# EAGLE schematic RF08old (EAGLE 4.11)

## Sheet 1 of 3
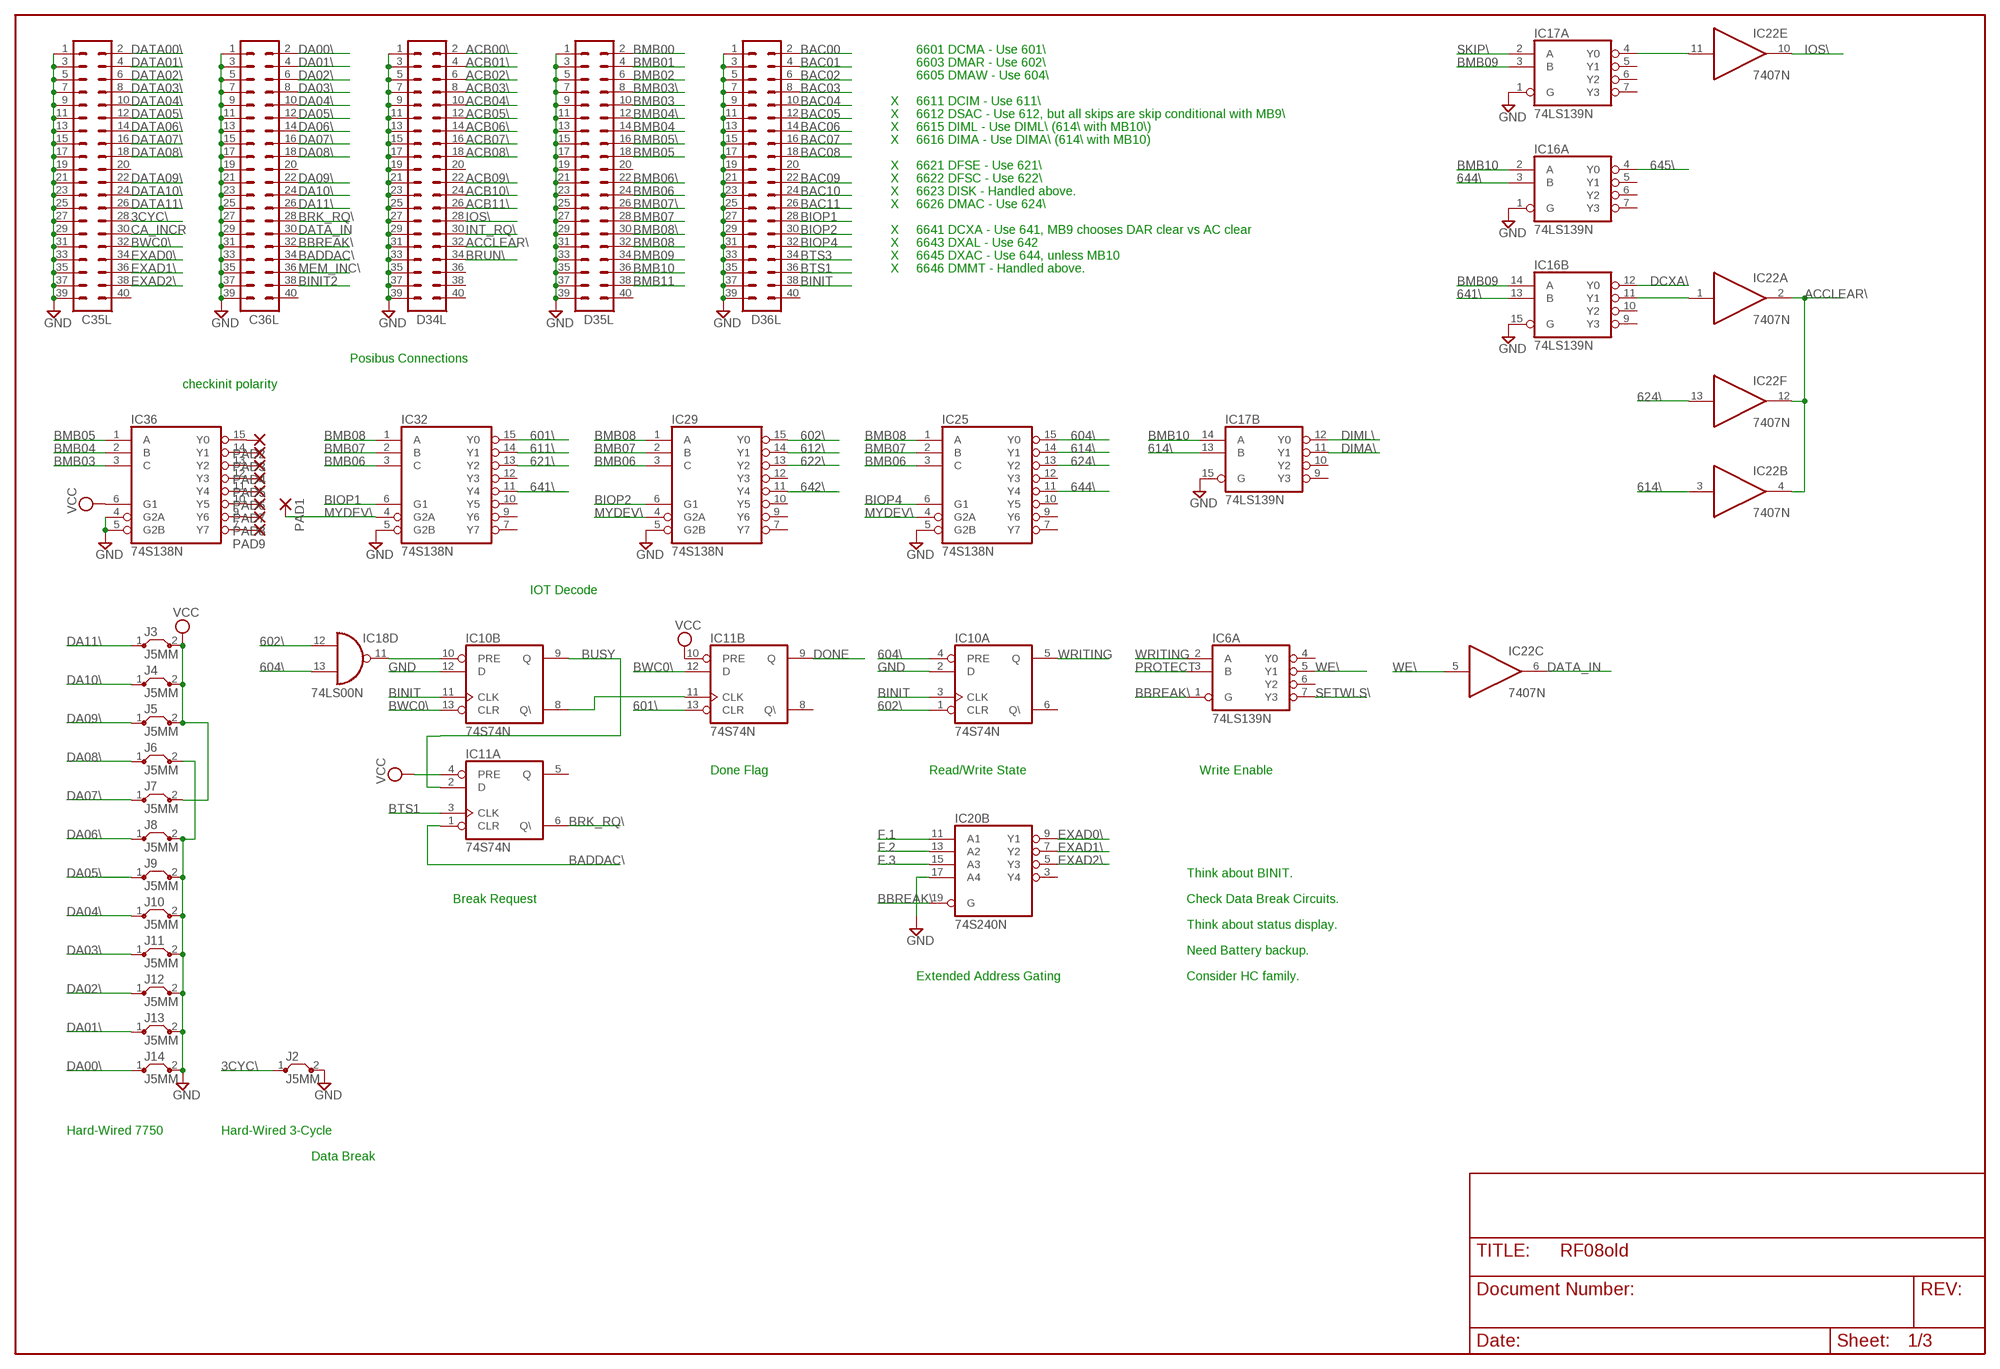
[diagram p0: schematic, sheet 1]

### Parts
C35L  MA20-2  [MA20-2]
C36L  MA20-2  [MA20-2]
D34L  MA20-2  [MA20-2]
D35L  MA20-2  [MA20-2]
D36L  MA20-2  [MA20-2]
IC6  74LS139N  74S139N  [DIL16]
IC10  74S74N  [DIL14]
IC11  74S74N  [DIL14]
IC16  74LS139N  74S139N  [DIL16]
IC17  74LS139N  74S139N  [DIL16]
IC18  74LS00N  [DIL14]
IC20  74S240N  [DIL20]
IC22  7407N  [DIL14]
IC25  74S138N  [DIL16]
IC29  74S138N  [DIL16]
IC32  74S138N  [DIL16]
IC36  74S138N  [DIL16]
J2  J5MM  [05]
J3  J5MM  [05]
J4  J5MM  [05]
J5  J5MM  [05]
J6  J5MM  [05]
J7  J5MM  [05]
J8  J5MM  [05]
J9  J5MM  [05]
J10  J5MM  [05]
J11  J5MM  [05]
J12  J5MM  [05]
J13  J5MM  [05]
J14  J5MM  [05]
PAD1  1,6/0,8  [1,6/0,8]
PAD2  1,6/0,8  [1,6/0,8]
PAD3  1,6/0,8  [1,6/0,8]
PAD4  1,6/0,8  [1,6/0,8]
PAD5  1,6/0,8  [1,6/0,8]
PAD6  1,6/0,8  [1,6/0,8]
PAD7  1,6/0,8  [1,6/0,8]
PAD8  1,6/0,8  [1,6/0,8]
PAD9  1,6/0,8  [1,6/0,8]

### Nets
3CYC\: C35L.28 J2.1
601\: IC11.13(B:CLR) IC32.15(Y0) ; also sheet 2
602\: IC10.1(A:CLR) IC18.12(D:I0) IC29.15(Y0) ; also sheet 2
604\: IC10.4(A:PRE) IC18.13(D:I1) IC25.15(Y0) ; also sheet 2
611\: IC32.14(Y1) ; also sheet 2
612\: IC29.14(Y1) ; also sheet 2
614\: IC17.13(B:B) IC22.3(B:I) IC25.14(Y1)
621\: IC32.13(Y2) ; also sheet 2
622\: IC29.13(Y2) ; also sheet 2
624\: IC22.13(F:I) IC25.13(Y2) ; also sheet 2
641\: IC16.13(B:B) IC32.11(Y4)
642\: IC29.11(Y4) ; also sheet 2
644\: IC16.3(A:B) IC25.11(Y4)
645\: IC16.4(A:Y0) ; also sheet 2
ACB00\: D34L.2 ; also sheet 2
ACB01\: D34L.4 ; also sheet 2
ACB02\: D34L.6 ; also sheet 2
ACB03\: D34L.8 ; also sheet 2
ACB04\: D34L.10 ; also sheet 2
ACB05\: D34L.12 ; also sheet 2
ACB06\: D34L.14 ; also sheet 2
ACB07\: D34L.16 ; also sheet 2
ACB08\: D34L.18 ; also sheet 2
ACB09\: D34L.22 ; also sheet 2
ACB10\: D34L.24 ; also sheet 2
ACB11\: D34L.26 ; also sheet 2
ACCLEAR\: D34L.32 IC22.2(A:O) IC22.4(B:O) IC22.12(F:O)
BAC00: D36L.2 ; also sheet 2
BAC01: D36L.4 ; also sheet 2
BAC02: D36L.6 ; also sheet 2
BAC03: D36L.8 ; also sheet 2
BAC04: D36L.10 ; also sheet 2
BAC05: D36L.12 ; also sheet 2
BAC06: D36L.14 ; also sheet 2
BAC07: D36L.16 ; also sheet 2
BAC08: D36L.18 ; also sheet 2
BAC09: D36L.22 ; also sheet 2
BAC10: D36L.24 ; also sheet 2
BAC11: D36L.26 ; also sheet 2
BADDAC\: C36L.34 IC11.1(A:CLR)
BBREAK\: C36L.32 IC6.1(A:G) IC20.19(B:G) ; also sheet 2,3
BINIT: D36L.38 IC10.3(A:CLK) IC10.11(B:CLK) ; also sheet 2
BINIT2: C36L.38
BIOP1: D36L.28 IC32.6(G1)
BIOP2: D36L.30 IC29.6(G1)
BIOP4: D36L.32 IC25.6(G1)
BMB00: D35L.2 ; also sheet 3
BMB01: D35L.4 ; also sheet 3
BMB02: D35L.6 ; also sheet 3
BMB03: D35L.10 IC36.3(C) ; also sheet 3
BMB03\: D35L.8
BMB04: D35L.14 IC36.2(B) ; also sheet 3
BMB04\: D35L.12
BMB05: D35L.18 IC36.1(A) ; also sheet 3
BMB05\: D35L.16
BMB06: D35L.24 IC25.3(C) IC29.3(C) IC32.3(C) ; also sheet 3
BMB06\: D35L.22
BMB07: D35L.28 IC25.2(B) IC29.2(B) IC32.2(B) ; also sheet 3
BMB07\: D35L.26
BMB08: D35L.32 IC25.1(A) IC29.1(A) IC32.1(A) ; also sheet 3
BMB08\: D35L.30
BMB09: D35L.34 IC16.14(B:A) IC17.3(A:B) ; also sheet 3
BMB10: D35L.36 IC16.2(A:A) IC17.14(B:A) ; also sheet 3
BMB11: D35L.38 ; also sheet 3
BRK_RQ\: C36L.28 IC11.6(A:Q\) ; also sheet 3
BRUN\: D34L.34
BTS1: D36L.36 IC11.3(A:CLK)
BTS3: D36L.34
BUSY: IC10.9(B:Q) IC11.2(A:D) ; also sheet 2
BWC0\: C35L.32 IC10.13(B:CLR) IC11.12(B:D) ; also sheet 3
CA_INCR: C35L.30
DA00\: C36L.2 J14.1
DA01\: C36L.4 J13.1
DA02\: C36L.6 J12.1
DA03\: C36L.8 J11.1
DA04\: C36L.10 J10.1
DA05\: C36L.12 J9.1
DA06\: C36L.14 J8.1
DA07\: C36L.16 J7.1
DA08\: C36L.18 J6.1
DA09\: C36L.22 J5.1
DA10\: C36L.24 J4.1
DA11\: C36L.26 J3.1
DATA00\: C35L.2 ; also sheet 3
DATA01\: C35L.4 ; also sheet 3
DATA02\: C35L.6 ; also sheet 3
DATA03\: C35L.8 ; also sheet 3
DATA04\: C35L.10 ; also sheet 3
DATA05\: C35L.12 ; also sheet 3
DATA06\: C35L.14 ; also sheet 3
DATA07\: C35L.16 ; also sheet 3
DATA08\: C35L.18 ; also sheet 3
DATA09\: C35L.22 ; also sheet 3
DATA10\: C35L.24 ; also sheet 3
DATA11\: C35L.26 ; also sheet 3
DATA_IN: C36L.30 IC22.6(C:O)
DCXA\: IC16.12(B:Y0) ; also sheet 2
DIMA\: IC17.11(B:Y1) ; also sheet 2
DIML\: IC17.12(B:Y0) ; also sheet 2
DONE: IC11.9(B:Q) ; also sheet 2,3
EXAD0\: C35L.34 IC20.9(B:Y1)
EXAD1\: C35L.36 IC20.7(B:Y2)
EXAD2\: C35L.38 IC20.5(B:Y3)
F.1: IC20.11(B:A1) ; also sheet 2,3
F.2: IC20.13(B:A2) ; also sheet 2,3
F.3: IC20.15(B:A3) ; also sheet 2,3
GND: C35L.1 C35L.3 C35L.5 C35L.7 C35L.9 C35L.11 C35L.13 C35L.15 C35L.17 C35L.19 C35L.21 C35L.23 C35L.25 C35L.27 C35L.29 C35L.31 C35L.33 C35L.35 C35L.37 C35L.39 C36L.1 C36L.3 C36L.5 C36L.7 C36L.9 C36L.11 C36L.13 C36L.15 C36L.17 C36L.19 C36L.21 C36L.23 C36L.25 C36L.27 C36L.29 C36L.31 C36L.33 C36L.35 C36L.37 C36L.39 D34L.1 D34L.3 D34L.5 D34L.7 D34L.9 D34L.11 D34L.13 D34L.15 D34L.17 D34L.19 D34L.21 D34L.23 D34L.25 D34L.27 D34L.29 D34L.31 D34L.33 D34L.35 D34L.37 D34L.39 D35L.1 D35L.3 D35L.5 D35L.7 D35L.9 D35L.11 D35L.13 D35L.15 D35L.17 D35L.19 D35L.21 D35L.23 D35L.25 D35L.27 D35L.29 D35L.31 D35L.33 D35L.35 D35L.37 D35L.39 D36L.1 D36L.3 D36L.5 D36L.7 D36L.9 D36L.11 D36L.13 D36L.15 D36L.17 D36L.19 D36L.21 D36L.23 D36L.25 D36L.27 D36L.29 D36L.31 D36L.33 D36L.35 D36L.37 D36L.39 IC10.2(A:D) IC10.12(B:D) IC16.1(A:G) IC16.15(B:G) IC17.1(A:G) IC17.15(B:G) IC20.17(B:A4) IC25.5(G2B) IC29.5(G2B) IC32.5(G2B) IC36.4(G2A) IC36.5(G2B) J2.2 J6.2 J8.2 J9.2 J10.2 J11.2 J12.2 J13.2 J14.2 ; also sheet 2,3
INT_RQ\: D34L.30 ; also sheet 2
IOS\: D34L.28 IC22.10(E:O)
MEM_INC\: C36L.36
MYDEV\: IC25.4(G2A) IC29.4(G2A) IC32.4(G2A) PAD1.1(P)
N$1: IC36.9(Y6) PAD8.1(P)
N$2: IC10.8(B:Q\) IC11.11(B:CLK)
N$5: IC36.15(Y0) PAD2.1(P)
N$6: IC36.14(Y1) PAD3.1(P)
N$7: IC36.13(Y2) PAD4.1(P)
N$8: IC36.12(Y3) PAD5.1(P)
N$9: IC36.11(Y4) PAD6.1(P)
N$10: IC36.10(Y5) PAD7.1(P)
N$11: IC36.7(Y7) PAD9.1(P)
N$26: IC16.11(B:Y1) IC22.1(A:I)
N$27: IC17.4(A:Y0) IC22.11(E:I)
N$31: IC10.10(B:PRE) IC18.11(D:O)
PROTECT: IC6.3(A:B) ; also sheet 3
SETWLS\: IC6.7(A:Y3) ; also sheet 2
SKIP\: IC17.2(A:A) ; also sheet 2
VCC [Power]: IC11.4(A:PRE) IC11.10(B:PRE) IC36.6(G1) J3.2 J4.2 J5.2 J7.2 ; also sheet 2,3
WE\: IC6.5(A:Y1) IC22.5(C:I) ; also sheet 3
WRITING: IC6.2(A:A) IC10.5(A:Q) ; also sheet 3
Unconnected: C35L.20 C35L.40 C36L.20 C36L.40 D34L.20 D34L.36 D34L.38 D34L.40 D35L.20 D35L.40 D36L.20 D36L.40 IC6.4(A:Y0) IC6.6(A:Y2) IC6.9(B:Y3) IC6.10(B:Y2) IC6.11(B:Y1) IC6.12(B:Y0) IC6.13(B:B) IC6.14(B:A) IC6.15(B:G) IC10.6(A:Q\) IC11.5(A:Q) IC11.8(B:Q\) IC16.5(A:Y1) IC16.6(A:Y2) IC16.7(A:Y3) IC16.9(B:Y3) IC16.10(B:Y2) IC17.5(A:Y1) IC17.6(A:Y2) IC17.7(A:Y3) IC17.9(B:Y3) IC17.10(B:Y2) IC20.1(A:G) IC20.2(A:A1) IC20.3(B:Y4) IC20.4(A:A2) IC20.6(A:A3) IC20.8(A:A4) IC20.12(A:Y4) IC20.14(A:Y3) IC20.16(A:Y2) IC20.18(A:Y1) IC22.8(D:O) IC22.9(D:I) IC25.7(Y7) IC25.9(Y6) IC25.10(Y5) IC25.12(Y3) IC29.7(Y7) IC29.9(Y6) IC29.10(Y5) IC29.12(Y3) IC32.7(Y7) IC32.9(Y6) IC32.10(Y5) IC32.12(Y3)

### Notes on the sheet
- 6601 DCMA - Use 601\
- 6603 DMAR - Use 602\
- 6605 DMAW - Use 604\
- X | 6611 DCIM - Use 611\
- X | 6612 DSAC - Use 612\, but all skips are skip conditional with MB9\
- X | 6615 DIML - Use DIML\ (614\ with MB10\)
- X | 6616 DIMA - Use DIMA\ (614\ with MB10)
- X | 6621 DFSE - Use 621\
- X | 6622 DFSC - Use 622\
- X | 6623 DISK - Handled above.
- X | 6626 DMAC - Use 624\
- X | 6641 DCXA - Use 641, MB9 chooses DAR clear vs AC clear
- X | 6643 DXAL - Use 642
- X | 6645 DXAC - Use 644, unless MB10
- X | 6646 DMMT - Handled above.
- Posibus Connections
- checkinit polarity
- IOT Decode
- Done Flag | Read/Write State | Write Enable
- Think about BINIT.
- Break Request | Check Data Break Circuits.
- Think about status display.
- Need Battery backup.
- Extended Address Gating | Consider HC family.
- Hard-Wired 7750 | Hard-Wired 3-Cycle
- Data Break

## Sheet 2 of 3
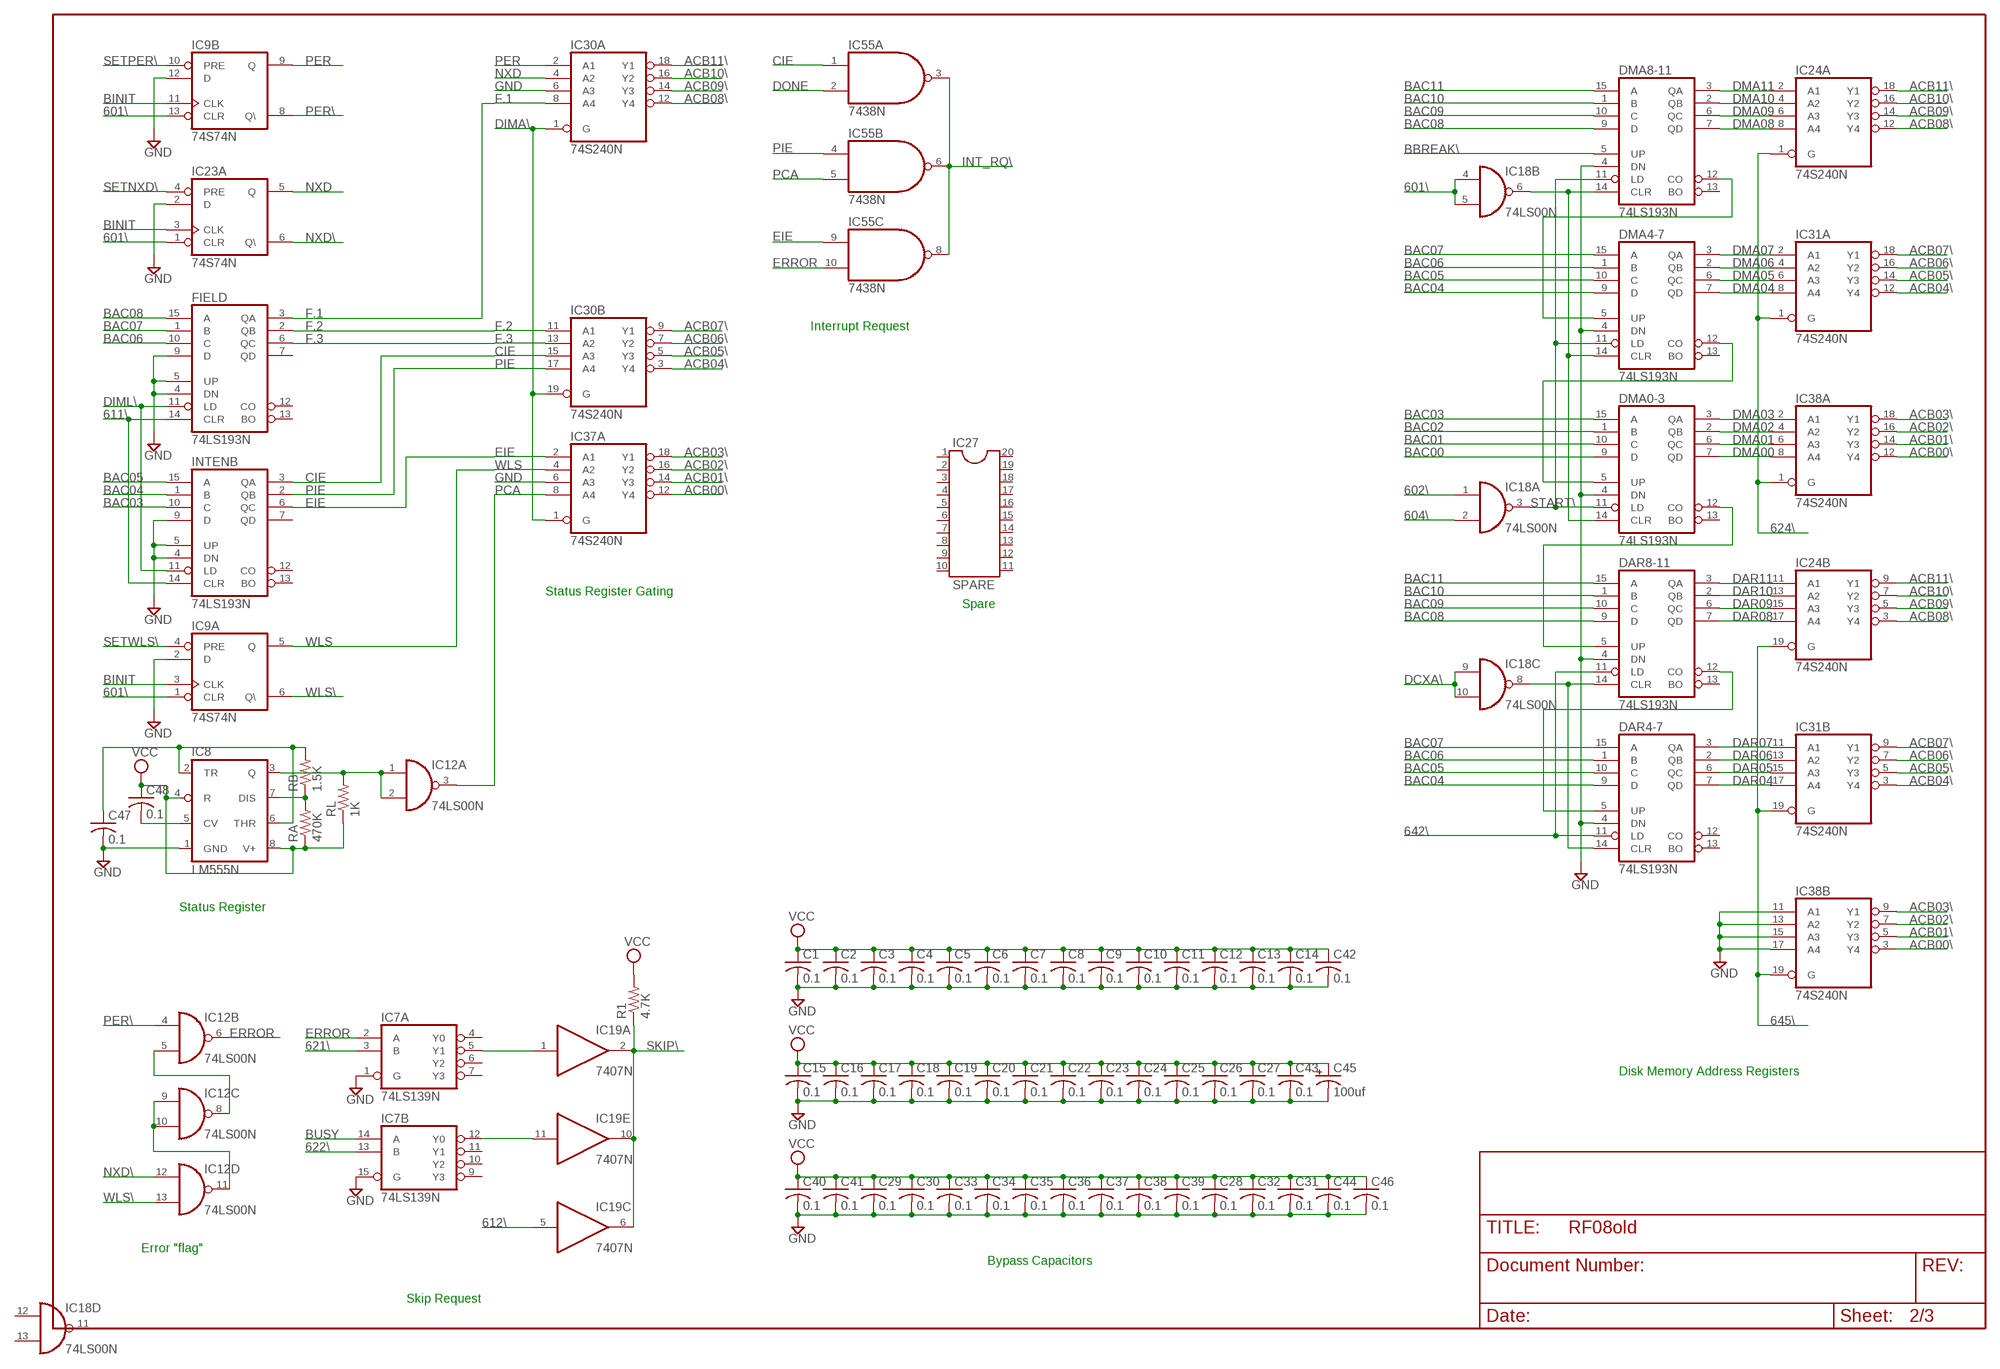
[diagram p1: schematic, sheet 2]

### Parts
C1  0.1  C-US050-025X075  [C050-025X075]
C2  0.1  C-US050-025X075  [C050-025X075]
C3  0.1  C-US050-025X075  [C050-025X075]
C4  0.1  C-US050-025X075  [C050-025X075]
C5  0.1  C-US050-025X075  [C050-025X075]
C6  0.1  C-US050-025X075  [C050-025X075]
C7  0.1  C-US050-025X075  [C050-025X075]
C8  0.1  C-US050-025X075  [C050-025X075]
C9  0.1  C-US050-025X075  [C050-025X075]
C10  0.1  C-US050-025X075  [C050-025X075]
C11  0.1  C-US050-025X075  [C050-025X075]
C12  0.1  C-US050-025X075  [C050-025X075]
C13  0.1  C-US050-025X075  [C050-025X075]
C14  0.1  C-US050-025X075  [C050-025X075]
C15  0.1  C-US050-025X075  [C050-025X075]
C16  0.1  C-US050-025X075  [C050-025X075]
C17  0.1  C-US050-025X075  [C050-025X075]
C18  0.1  C-US050-025X075  [C050-025X075]
C19  0.1  C-US050-025X075  [C050-025X075]
C20  0.1  C-US050-025X075  [C050-025X075]
C21  0.1  C-US050-025X075  [C050-025X075]
C22  0.1  C-US050-025X075  [C050-025X075]
C23  0.1  C-US050-025X075  [C050-025X075]
C24  0.1  C-US050-025X075  [C050-025X075]
C25  0.1  C-US050-025X075  [C050-025X075]
C26  0.1  C-US050-025X075  [C050-025X075]
C27  0.1  C-US050-025X075  [C050-025X075]
C28  0.1  C-US050-025X075  [C050-025X075]
C29  0.1  C-US050-025X075  [C050-025X075]
C30  0.1  C-US050-025X075  [C050-025X075]
C31  0.1  C-US050-025X075  [C050-025X075]
C32  0.1  C-US050-025X075  [C050-025X075]
C33  0.1  C-US050-025X075  [C050-025X075]
C34  0.1  C-US050-025X075  [C050-025X075]
C35  0.1  C-US050-025X075  [C050-025X075]
C36  0.1  C-US050-025X075  [C050-025X075]
C37  0.1  C-US050-025X075  [C050-025X075]
C38  0.1  C-US050-025X075  [C050-025X075]
C39  0.1  C-US050-025X075  [C050-025X075]
C40  0.1  C-US050-025X075  [C050-025X075]
C41  0.1  C-US050-025X075  [C050-025X075]
C42  0.1  C-US050-025X075  [C050-025X075]
C43  0.1  C-US050-025X075  [C050-025X075]
C44  0.1  C-US050-025X075  [C050-025X075]
C45  100uf  CPOL-USE22-6AXIAL  [E22-6]
C46  0.1  C-US050-025X075  [C050-025X075]
C47  0.1  C-US050-025X075  [C050-025X075]
C48  0.1  C-US050-025X075  [C050-025X075]
DAR4-7  74LS193N  74LS192N  [DIL16]
DAR8-11  74LS193N  74LS192N  [DIL16]
DMA0-3  74LS193N  74LS192N  [DIL16]
DMA4-7  74LS193N  74LS192N  [DIL16]
DMA8-11  74LS193N  74LS192N  [DIL16]
FIELD  74LS193N  74LS192N  [DIL16]
IC7  74LS139N  [DIL16]
IC8  LM555N  [DIL08]
IC9  74S74N  [DIL14]
IC12  74LS00N  [DIL14]
IC19  7407N  [DIL14]
IC23  74S74N  [DIL14]
IC24  74S240N  [DIL20]
IC27  SPARE  DIL20  [DIL20]
IC30  74S240N  [DIL20]
IC31  74S240N  [DIL20]
IC37  74S240N  [DIL20]
IC38  74S240N  [DIL20]
IC55  7438N  [DIL14]
INTENB  74LS193N  74LS192N  [DIL16]
R1  4.7K  R-US_0207/10  [0207/10]
RA  470K  R-US_0207/10  [0207/10]
RB  1.5K  R-US_0207/10  [0207/10]
RL  1K  R-US_0207/10  [0207/10]

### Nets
601\: IC9.1(A:CLR) IC9.13(B:CLR) IC18.4(B:I0) IC18.5(B:I1) IC23.1(A:CLR) ; also sheet 1
602\: IC18.1(A:I0) ; also sheet 1
604\: IC18.2(A:I1) ; also sheet 1
611\: FIELD.14(CLR) INTENB.14(CLR) ; also sheet 1
612\: IC19.5(C:I) ; also sheet 1
621\: IC7.3(A:B) ; also sheet 1
622\: IC7.13(B:B) ; also sheet 1
624\: IC24.1(A:G) IC31.1(A:G) IC38.1(A:G) ; also sheet 1
642\: DAR4-7.11(LD) DAR8-11.11(LD) ; also sheet 1
645\: IC24.19(B:G) IC31.19(B:G) IC38.19(B:G) ; also sheet 1
ACB00\: IC37.12(A:Y4) IC38.3(B:Y4) IC38.12(A:Y4) ; also sheet 1
ACB01\: IC37.14(A:Y3) IC38.5(B:Y3) IC38.14(A:Y3) ; also sheet 1
ACB02\: IC37.16(A:Y2) IC38.7(B:Y2) IC38.16(A:Y2) ; also sheet 1
ACB03\: IC37.18(A:Y1) IC38.9(B:Y1) IC38.18(A:Y1) ; also sheet 1
ACB04\: IC30.3(B:Y4) IC31.3(B:Y4) IC31.12(A:Y4) ; also sheet 1
ACB05\: IC30.5(B:Y3) IC31.5(B:Y3) IC31.14(A:Y3) ; also sheet 1
ACB06\: IC30.7(B:Y2) IC31.7(B:Y2) IC31.16(A:Y2) ; also sheet 1
ACB07\: IC30.9(B:Y1) IC31.9(B:Y1) IC31.18(A:Y1) ; also sheet 1
ACB08\: IC24.3(B:Y4) IC24.12(A:Y4) IC30.12(A:Y4) ; also sheet 1
ACB09\: IC24.5(B:Y3) IC24.14(A:Y3) IC30.14(A:Y3) ; also sheet 1
ACB10\: IC24.7(B:Y2) IC24.16(A:Y2) IC30.16(A:Y2) ; also sheet 1
ACB11\: IC24.9(B:Y1) IC24.18(A:Y1) IC30.18(A:Y1) ; also sheet 1
BAC00: DMA0-3.9(D) ; also sheet 1
BAC01: DMA0-3.10(C) ; also sheet 1
BAC02: DMA0-3.1(B) ; also sheet 1
BAC03: DMA0-3.15(A) INTENB.10(C) ; also sheet 1
BAC04: DAR4-7.9(D) DMA4-7.9(D) INTENB.1(B) ; also sheet 1
BAC05: DAR4-7.10(C) DMA4-7.10(C) INTENB.15(A) ; also sheet 1
BAC06: DAR4-7.1(B) DMA4-7.1(B) FIELD.10(C) ; also sheet 1
BAC07: DAR4-7.15(A) DMA4-7.15(A) FIELD.1(B) ; also sheet 1
BAC08: DAR8-11.9(D) DMA8-11.9(D) FIELD.15(A) ; also sheet 1
BAC09: DAR8-11.10(C) DMA8-11.10(C) ; also sheet 1
BAC10: DAR8-11.1(B) DMA8-11.1(B) ; also sheet 1
BAC11: DAR8-11.15(A) DMA8-11.15(A) ; also sheet 1
BBREAK\: DMA8-11.5(UP) ; also sheet 1,3
BINIT: IC9.3(A:CLK) IC9.11(B:CLK) IC23.3(A:CLK) ; also sheet 1
BUSY: IC7.14(B:A) ; also sheet 1
CIE: IC30.15(B:A3) IC55.1(A:I0) INTENB.3(QA) ; also sheet 3
DAR04: DAR4-7.7(QD) IC31.17(B:A4) ; also sheet 3
DAR05: DAR4-7.6(QC) IC31.15(B:A3) ; also sheet 3
DAR06: DAR4-7.2(QB) IC31.13(B:A2) ; also sheet 3
DAR07: DAR4-7.3(QA) IC31.11(B:A1) ; also sheet 3
DAR08: DAR8-11.7(QD) IC24.17(B:A4) ; also sheet 3
DAR09: DAR8-11.6(QC) IC24.15(B:A3) ; also sheet 3
DAR10: DAR8-11.2(QB) IC24.13(B:A2) ; also sheet 3
DAR11: DAR8-11.3(QA) IC24.11(B:A1) ; also sheet 3
DCXA\: IC18.9(C:I0) IC18.10(C:I1) ; also sheet 1
DIMA\: IC30.1(A:G) IC30.19(B:G) IC37.1(A:G) ; also sheet 1
DIML\: FIELD.11(LD) INTENB.11(LD) ; also sheet 1
DMA00: DMA0-3.7(QD) IC38.8(A:A4) ; also sheet 3
DMA01: DMA0-3.6(QC) IC38.6(A:A3) ; also sheet 3
DMA02: DMA0-3.2(QB) IC38.4(A:A2) ; also sheet 3
DMA03: DMA0-3.3(QA) IC38.2(A:A1) ; also sheet 3
DMA04: DMA4-7.7(QD) IC31.8(A:A4) ; also sheet 3
DMA05: DMA4-7.6(QC) IC31.6(A:A3) ; also sheet 3
DMA06: DMA4-7.2(QB) IC31.4(A:A2) ; also sheet 3
DMA07: DMA4-7.3(QA) IC31.2(A:A1) ; also sheet 3
DMA08: DMA8-11.7(QD) IC24.8(A:A4) ; also sheet 3
DMA09: DMA8-11.6(QC) IC24.6(A:A3) ; also sheet 3
DMA10: DMA8-11.2(QB) IC24.4(A:A2) ; also sheet 3
DMA11: DMA8-11.3(QA) IC24.2(A:A1) ; also sheet 3
DONE: IC55.2(A:I1) ; also sheet 1,3
EIE: IC37.2(A:A1) IC55.9(C:I0) INTENB.6(QC) ; also sheet 3
ERROR: IC7.2(A:A) IC12.6(B:O) IC55.10(C:I1)
F.1: FIELD.3(QA) IC30.8(A:A4) ; also sheet 1,3
F.2: FIELD.2(QB) IC30.11(B:A1) ; also sheet 1,3
F.3: FIELD.6(QC) IC30.13(B:A2) ; also sheet 1,3
GND: C1.2 C2.2 C3.2 C4.2 C5.2 C6.2 C7.2 C8.2 C9.2 C10.2 C11.2 C12.2 C13.2 C14.2 C15.2 C16.2 C17.2 C18.2 C19.2 C20.2 C21.2 C22.2 C23.2 C24.2 C25.2 C26.2 C27.2 C28.2 C29.2 C30.2 C31.2 C32.2 C33.2 C34.2 C35.2 C36.2 C37.2 C38.2 C39.2 C40.2 C41.2 C42.2 C43.2 C44.2 C45.- C46.2 C47.2 DAR4-7.4(DN) DAR8-11.4(DN) DMA0-3.4(DN) DMA4-7.4(DN) DMA8-11.4(DN) FIELD.4(DN) FIELD.5(UP) FIELD.9(D) IC7.1(A:G) IC7.15(B:G) IC8.1(GND) IC9.2(A:D) IC9.12(B:D) IC23.2(A:D) IC30.6(A:A3) IC37.6(A:A3) IC38.11(B:A1) IC38.13(B:A2) IC38.15(B:A3) IC38.17(B:A4) INTENB.4(DN) INTENB.5(UP) INTENB.9(D) ; also sheet 1,3
INT_RQ\: IC55.3(A:O) IC55.6(B:O) IC55.8(C:O) ; also sheet 1
N$3: DMA0-3.5(UP) DMA4-7.12(CO)
N$12: DAR4-7.14(CLR) DAR8-11.14(CLR) IC18.8(C:O)
N$13: DMA4-7.5(UP) DMA8-11.12(CO)
N$16: DAR8-11.5(UP) DMA0-3.12(CO)
N$22: DMA0-3.14(CLR) DMA4-7.14(CLR) DMA8-11.14(CLR) IC18.6(B:O)
N$25: DAR4-7.5(UP) DAR8-11.12(CO)
N$28: IC7.5(A:Y1) IC19.1(A:I)
N$29: IC8.7(DIS) RA.2 RB.1
N$30: IC8.3(Q) IC12.1(A:I0) IC12.2(A:I1) RL.2
N$32: C47.1 IC8.2(TR) IC8.6(THR) RB.2
N$33: IC7.12(B:Y0) IC19.11(E:I)
N$34: C48.2 IC8.5(CV)
N$37: IC12.9(C:I0) IC12.10(C:I1) IC12.11(D:O)
N$40: IC12.5(B:I1) IC12.8(C:O)
NXD: IC23.5(A:Q) IC30.4(A:A2) ; also sheet 3
NXD\: IC12.12(D:I0) IC23.6(A:Q\)
PCA: IC12.3(A:O) IC37.8(A:A4) IC55.5(B:I1)
PER: IC9.9(B:Q) IC30.2(A:A1) ; also sheet 3
PER\: IC9.8(B:Q\) IC12.4(B:I0)
PIE: IC30.17(B:A4) IC55.4(B:I0) INTENB.2(QB) ; also sheet 3
SETNXD\: IC23.4(A:PRE) ; also sheet 3
SETPER\: IC9.10(B:PRE) ; also sheet 3
SETWLS\: IC9.4(A:PRE) ; also sheet 1
SKIP\: IC19.2(A:O) IC19.6(C:O) IC19.10(E:O) R1.1 ; also sheet 1
START\: DMA0-3.11(LD) DMA4-7.11(LD) DMA8-11.11(LD) IC18.3(A:O)
VCC [Power]: C1.1 C2.1 C3.1 C4.1 C5.1 C6.1 C7.1 C8.1 C9.1 C10.1 C11.1 C12.1 C13.1 C14.1 C15.1 C16.1 C17.1 C18.1 C19.1 C20.1 C21.1 C22.1 C23.1 C24.1 C25.1 C26.1 C27.1 C28.1 C29.1 C30.1 C31.1 C32.1 C33.1 C34.1 C35.1 C36.1 C37.1 C38.1 C39.1 C40.1 C41.1 C42.1 C43.1 C44.1 C45.+ C46.1 C48.1 IC8.4(R) IC8.8(V+) R1.2 RA.1 RL.1 ; also sheet 1,3
WLS: IC9.5(A:Q) IC37.4(A:A2) ; also sheet 3
WLS\: IC9.6(A:Q\) IC12.13(D:I1)
Unconnected: DAR4-7.12(CO) DAR4-7.13(BO) DAR8-11.13(BO) DMA0-3.13(BO) DMA4-7.13(BO) DMA8-11.13(BO) FIELD.7(QD) FIELD.12(CO) FIELD.13(BO) IC7.4(A:Y0) IC7.6(A:Y2) IC7.7(A:Y3) IC7.9(B:Y3) IC7.10(B:Y2) IC7.11(B:Y1) IC19.3(B:I) IC19.4(B:O) IC19.8(D:O) IC19.9(D:I) IC19.12(F:O) IC19.13(F:I) IC23.8(B:Q\) IC23.9(B:Q) IC23.10(B:PRE) IC23.11(B:CLK) IC23.12(B:D) IC23.13(B:CLR) IC27.1 IC27.2 IC27.3 IC27.4 IC27.5 IC27.6 IC27.7 IC27.8 IC27.9 IC27.10 IC27.11 IC27.12 IC27.13 IC27.14 IC27.15 IC27.16 IC27.17 IC27.18 IC27.19 IC27.20 IC37.3(B:Y4) IC37.5(B:Y3) IC37.7(B:Y2) IC37.9(B:Y1) IC37.11(B:A1) IC37.13(B:A2) IC37.15(B:A3) IC37.17(B:A4) IC37.19(B:G) IC55.11(D:O) IC55.12(D:I0) IC55.13(D:I1) INTENB.7(QD) INTENB.12(CO) INTENB.13(BO)

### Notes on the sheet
- Interrupt Request
- Status Register Gating
- Spare
- Status Register
- Disk Memory Address Registers
- Error "flag"
- Bypass Capacitors
- Skip Request

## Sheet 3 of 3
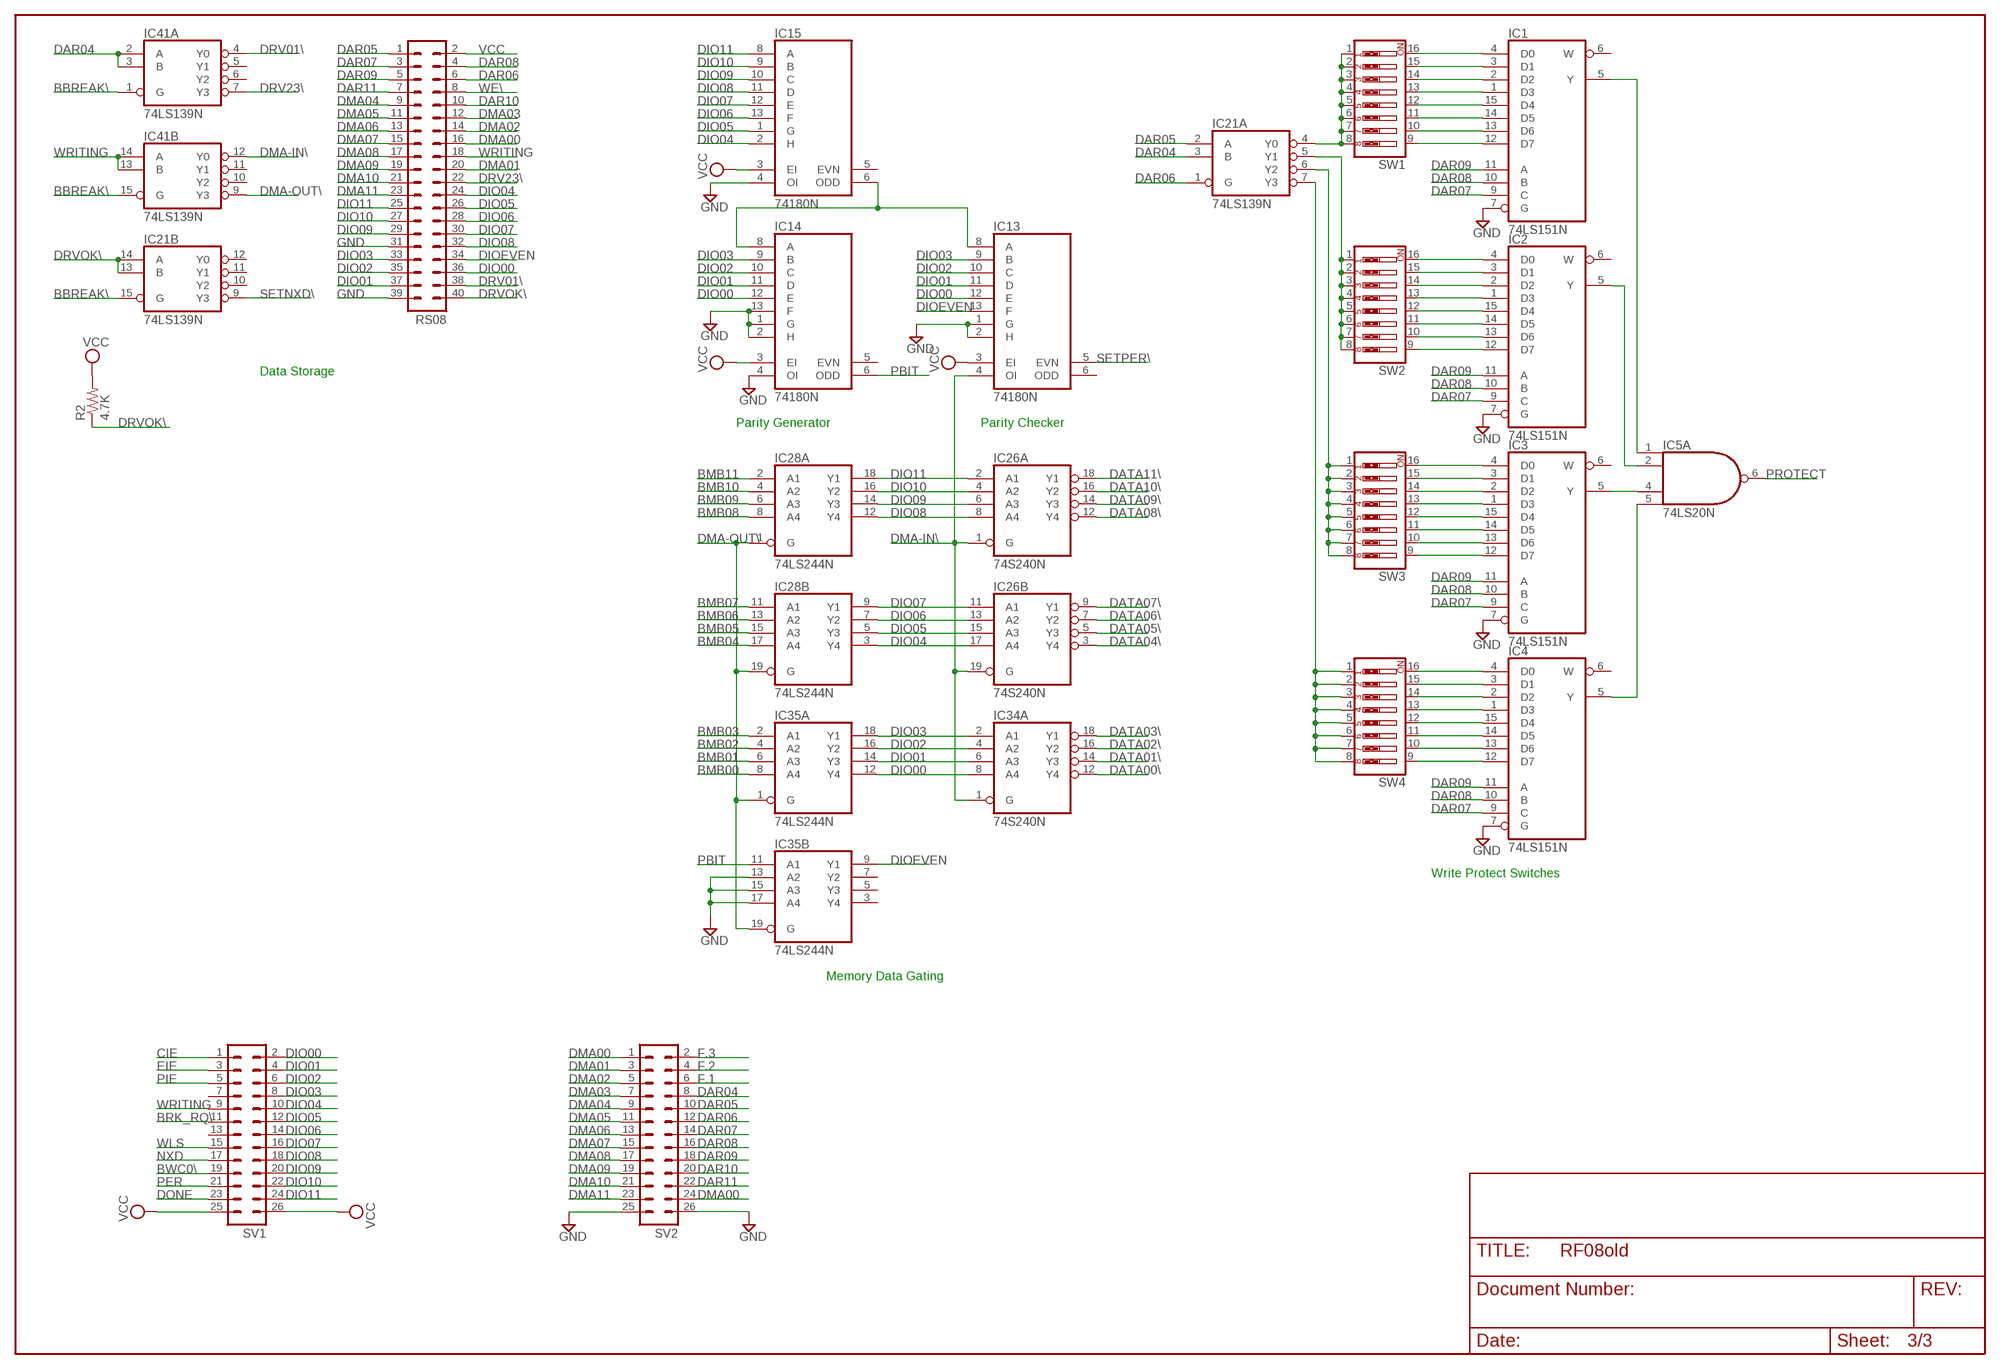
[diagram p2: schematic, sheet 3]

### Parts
IC1  74LS151N  [DIL16]
IC2  74LS151N  [DIL16]
IC3  74LS151N  [DIL16]
IC4  74LS151N  [DIL16]
IC5  74LS20N  [DIL14]
IC13  74180N  [DIL14]
IC14  74180N  [DIL14]
IC15  74180N  [DIL14]
IC21  74LS139N  [DIL16]
IC26  74S240N  [DIL20]
IC28  74LS244N  [DIL20]
IC34  74S240N  [DIL20]
IC35  74LS244N  [DIL20]
IC41  74LS139N  [DIL16]
R2  4.7K  R-US_0207/10  [0207/10]
RS08  MA20-2  [MA20-2]
SV1  MA13-2  [MA13-2]
SV2  MA13-2  [MA13-2]
SW1  SW_DIP-8  [EDG-08]
SW2  SW_DIP-8  [EDG-08]
SW3  SW_DIP-8  [EDG-08]
SW4  SW_DIP-8  [EDG-08]

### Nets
BBREAK\: IC21.15(B:G) IC41.1(A:G) IC41.15(B:G) ; also sheet 1,2
BMB00: IC35.8(A:A4) ; also sheet 1
BMB01: IC35.6(A:A3) ; also sheet 1
BMB02: IC35.4(A:A2) ; also sheet 1
BMB03: IC35.2(A:A1) ; also sheet 1
BMB04: IC28.17(B:A4) ; also sheet 1
BMB05: IC28.15(B:A3) ; also sheet 1
BMB06: IC28.13(B:A2) ; also sheet 1
BMB07: IC28.11(B:A1) ; also sheet 1
BMB08: IC28.8(A:A4) ; also sheet 1
BMB09: IC28.6(A:A3) ; also sheet 1
BMB10: IC28.4(A:A2) ; also sheet 1
BMB11: IC28.2(A:A1) ; also sheet 1
BRK_RQ\: SV1.11 ; also sheet 1
BWC0\: SV1.19 ; also sheet 1
CIE: SV1.1 ; also sheet 2
DAR04: IC21.3(A:B) IC41.2(A:A) IC41.3(A:B) SV2.8 ; also sheet 2
DAR05: IC21.2(A:A) RS08.1 SV2.10 ; also sheet 2
DAR06: IC21.1(A:G) RS08.6 SV2.12 ; also sheet 2
DAR07: IC1.9(C) IC2.9(C) IC3.9(C) IC4.9(C) RS08.3 SV2.14 ; also sheet 2
DAR08: IC1.10(B) IC2.10(B) IC3.10(B) IC4.10(B) RS08.4 SV2.16 ; also sheet 2
DAR09: IC1.11(A) IC2.11(A) IC3.11(A) IC4.11(A) RS08.5 SV2.18 ; also sheet 2
DAR10: RS08.10 SV2.20 ; also sheet 2
DAR11: RS08.7 SV2.22 ; also sheet 2
DATA00\: IC34.12(A:Y4) ; also sheet 1
DATA01\: IC34.14(A:Y3) ; also sheet 1
DATA02\: IC34.16(A:Y2) ; also sheet 1
DATA03\: IC34.18(A:Y1) ; also sheet 1
DATA04\: IC26.3(B:Y4) ; also sheet 1
DATA05\: IC26.5(B:Y3) ; also sheet 1
DATA06\: IC26.7(B:Y2) ; also sheet 1
DATA07\: IC26.9(B:Y1) ; also sheet 1
DATA08\: IC26.12(A:Y4) ; also sheet 1
DATA09\: IC26.14(A:Y3) ; also sheet 1
DATA10\: IC26.16(A:Y2) ; also sheet 1
DATA11\: IC26.18(A:Y1) ; also sheet 1
DIO00: IC13.12(E) IC14.12(E) IC34.8(A:A4) IC35.12(A:Y4) RS08.36 SV1.2
DIO01: IC13.11(D) IC14.11(D) IC34.6(A:A3) IC35.14(A:Y3) RS08.37 SV1.4
DIO02: IC13.10(C) IC14.10(C) IC34.4(A:A2) IC35.16(A:Y2) RS08.35 SV1.6
DIO03: IC13.9(B) IC14.9(B) IC34.2(A:A1) IC35.18(A:Y1) RS08.33 SV1.8
DIO04: IC15.2(H) IC26.17(B:A4) IC28.3(B:Y4) RS08.24 SV1.10
DIO05: IC15.1(G) IC26.15(B:A3) IC28.5(B:Y3) RS08.26 SV1.12
DIO06: IC15.13(F) IC26.13(B:A2) IC28.7(B:Y2) RS08.28 SV1.14
DIO07: IC15.12(E) IC26.11(B:A1) IC28.9(B:Y1) RS08.30 SV1.16
DIO08: IC15.11(D) IC26.8(A:A4) IC28.12(A:Y4) RS08.32 SV1.18
DIO09: IC15.10(C) IC26.6(A:A3) IC28.14(A:Y3) RS08.29 SV1.20
DIO10: IC15.9(B) IC26.4(A:A2) IC28.16(A:Y2) RS08.27 SV1.22
DIO11: IC15.8(A) IC26.2(A:A1) IC28.18(A:Y1) RS08.25 SV1.24
DIOEVEN: IC13.13(F) IC35.9(B:Y1) RS08.34
DMA00: RS08.16 SV2.1 SV2.24 ; also sheet 2
DMA01: RS08.20 SV2.3 ; also sheet 2
DMA02: RS08.14 SV2.5 ; also sheet 2
DMA03: RS08.12 SV2.7 ; also sheet 2
DMA04: RS08.9 SV2.9 ; also sheet 2
DMA05: RS08.11 SV2.11 ; also sheet 2
DMA06: RS08.13 SV2.13 ; also sheet 2
DMA07: RS08.15 SV2.15 ; also sheet 2
DMA08: RS08.17 SV2.17 ; also sheet 2
DMA09: RS08.19 SV2.19 ; also sheet 2
DMA10: RS08.21 SV2.21 ; also sheet 2
DMA11: RS08.23 SV2.23 ; also sheet 2
DMA-IN\: IC13.4(OI) IC26.1(A:G) IC26.19(B:G) IC34.1(A:G) IC41.12(B:Y0)
DMA-OUT\: IC28.1(A:G) IC28.19(B:G) IC35.1(A:G) IC35.19(B:G) IC41.9(B:Y3)
DONE: SV1.23 ; also sheet 1,2
DRV01\: IC41.4(A:Y0) RS08.38
DRV23\: IC41.7(A:Y3) RS08.22
DRVOK\: IC21.13(B:B) IC21.14(B:A) R2.1 RS08.40
EIE: SV1.3 ; also sheet 2
F.1: SV2.6 ; also sheet 1,2
F.2: SV2.4 ; also sheet 1,2
F.3: SV2.2 ; also sheet 1,2
GND: IC1.7(G) IC2.7(G) IC3.7(G) IC4.7(G) IC13.1(G) IC13.2(H) IC14.1(G) IC14.2(H) IC14.4(OI) IC14.13(F) IC15.4(OI) IC35.13(B:A2) IC35.15(B:A3) IC35.17(B:A4) RS08.31 RS08.39 SV2.25 SV2.26 ; also sheet 1,2
N$4: IC21.4(A:Y0) SW1.1 SW1.2 SW1.3 SW1.4 SW1.5 SW1.6 SW1.7 SW1.8
N$14: IC13.8(A) IC14.8(A) IC15.6(ODD)
N$15: IC2.5(Y) IC5.2(A:I1)
N$17: IC21.5(A:Y1) SW2.1 SW2.2 SW2.3 SW2.4 SW2.5 SW2.6 SW2.7 SW2.8
N$19: IC21.6(A:Y2) SW3.1 SW3.2 SW3.3 SW3.4 SW3.5 SW3.6 SW3.7 SW3.8
N$20: IC21.7(A:Y3) SW4.1 SW4.2 SW4.3 SW4.4 SW4.5 SW4.6 SW4.7 SW4.8
N$21: IC3.5(Y) IC5.4(A:I2)
N$23: IC1.5(Y) IC5.1(A:I0)
N$24: IC4.5(Y) IC5.5(A:I3)
N$53: IC1.4(D0) SW1.16
N$54: IC1.3(D1) SW1.15
N$55: IC1.2(D2) SW1.14
N$56: IC1.1(D3) SW1.13
N$57: IC1.14(D5) SW1.11
N$58: IC1.13(D6) SW1.10
N$59: IC1.12(D7) SW1.9
N$60: IC1.15(D4) SW1.12
N$61: IC2.4(D0) SW2.16
N$62: IC2.3(D1) SW2.15
N$63: IC2.2(D2) SW2.14
N$64: IC2.1(D3) SW2.13
N$65: IC2.14(D5) SW2.11
N$66: IC2.13(D6) SW2.10
N$67: IC2.12(D7) SW2.9
N$68: IC3.4(D0) SW3.16
N$69: IC3.3(D1) SW3.15
N$70: IC3.2(D2) SW3.14
N$71: IC3.1(D3) SW3.13
N$72: IC3.14(D5) SW3.11
N$73: IC3.13(D6) SW3.10
N$74: IC3.12(D7) SW3.9
N$75: IC4.4(D0) SW4.16
N$76: IC4.3(D1) SW4.15
N$77: IC4.2(D2) SW4.14
N$78: IC4.1(D3) SW4.13
N$79: IC4.14(D5) SW4.11
N$80: IC4.13(D6) SW4.10
N$81: IC4.12(D7) SW4.9
N$82: IC4.15(D4) SW4.12
N$83: IC3.15(D4) SW3.12
N$84: IC2.15(D4) SW2.12
NXD: SV1.17 ; also sheet 2
PBIT: IC14.6(ODD) IC35.11(B:A1)
PER: SV1.21 ; also sheet 2
PIE: SV1.5 ; also sheet 2
PROTECT: IC5.6(A:O) ; also sheet 1
SETNXD\: IC21.9(B:Y3) ; also sheet 2
SETPER\: IC13.5(EVN) ; also sheet 2
VCC [Power]: IC13.3(EI) IC14.3(EI) IC15.3(EI) R2.2 RS08.2 SV1.25 SV1.26 ; also sheet 1,2
WE\: RS08.8 ; also sheet 1
WLS: SV1.15 ; also sheet 2
WRITING: IC41.13(B:B) IC41.14(B:A) RS08.18 SV1.9 ; also sheet 1
Unconnected: IC1.6(W) IC2.6(W) IC3.6(W) IC4.6(W) IC5.8(B:O) IC5.9(B:I0) IC5.10(B:I1) IC5.12(B:I2) IC5.13(B:I3) IC13.6(ODD) IC14.5(EVN) IC15.5(EVN) IC21.10(B:Y2) IC21.11(B:Y1) IC21.12(B:Y0) IC34.3(B:Y4) IC34.5(B:Y3) IC34.7(B:Y2) IC34.9(B:Y1) IC34.11(B:A1) IC34.13(B:A2) IC34.15(B:A3) IC34.17(B:A4) IC34.19(B:G) IC35.3(B:Y4) IC35.5(B:Y3) IC35.7(B:Y2) IC41.5(A:Y1) IC41.6(A:Y2) IC41.10(B:Y2) IC41.11(B:Y1) SV1.7 SV1.13

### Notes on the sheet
- Data Storage
- Parity Generator | Parity Checker
- Write Protect Switches
- Memory Data Gating

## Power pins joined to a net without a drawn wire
GND: DAR4-7.8(GND) DAR8-11.8(GND) DMA0-3.8(GND) DMA4-7.8(GND) DMA8-11.8(GND) FIELD.8(GND) IC1.8(GND) IC2.8(GND) IC3.8(GND) IC4.8(GND) IC5.7(P:GND) IC6.8(P:GND) IC7.8(P:GND) IC9.7(P:GND) IC10.7(P:GND) IC11.7(P:GND) IC12.7(P:GND) IC13.7(GND) IC14.7(GND) IC15.7(GND) IC16.8(P:GND) IC17.8(P:GND) IC18.7(P:GND) IC19.7(P:GND) IC20.10(P:GND) IC21.8(P:GND) IC22.7(P:GND) IC23.7(P:GND) IC24.10(P:GND) IC25.8(GND) IC26.10(P:GND) IC28.10(P:GND) IC29.8(GND) IC30.10(P:GND) IC31.10(P:GND) IC32.8(GND) IC34.10(P:GND) IC35.10(P:GND) IC36.8(GND) IC37.10(P:GND) IC38.10(P:GND) IC41.8(P:GND) IC55.7(P:GND) INTENB.8(GND)
VCC: DAR4-7.16(VCC) DAR8-11.16(VCC) DMA0-3.16(VCC) DMA4-7.16(VCC) DMA8-11.16(VCC) FIELD.16(VCC) IC1.16(VCC) IC2.16(VCC) IC3.16(VCC) IC4.16(VCC) IC5.14(P:VCC) IC6.16(P:VCC) IC7.16(P:VCC) IC9.14(P:VCC) IC10.14(P:VCC) IC11.14(P:VCC) IC12.14(P:VCC) IC13.14(VCC) IC14.14(VCC) IC15.14(VCC) IC16.16(P:VCC) IC17.16(P:VCC) IC18.14(P:VCC) IC19.14(P:VCC) IC20.20(P:VCC) IC21.16(P:VCC) IC22.14(P:VCC) IC23.14(P:VCC) IC24.20(P:VCC) IC25.16(VCC) IC26.20(P:VCC) IC28.20(P:VCC) IC29.16(VCC) IC30.20(P:VCC) IC31.20(P:VCC) IC32.16(VCC) IC34.20(P:VCC) IC35.20(P:VCC) IC36.16(VCC) IC37.20(P:VCC) IC38.20(P:VCC) IC41.16(P:VCC) IC55.14(P:VCC) INTENB.16(VCC)

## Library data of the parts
C1-C44 C46-C48 = rcl:C-US: CAPACITOR, American symbol
C35L C36L D34L D35L D36L RS08 = con-lstb:MA20-2: PIN HEADER
C45 = rcl:CPOL-US: POLARIZED CAPACITOR, American symbol
DAR4-7 DAR8-11 DMA0-3 DMA4-7 DMA8-11 FIELD INTENB = 74xx-us:74*192: Synchronous 4-bit UP/DOWN COUNTER
IC1-IC4 = 74xx-eu:74*151: Data SELECTOR/MULTIPLEXER
IC5 = 74xx-us:74*20: Dual 4-input NAND gate
IC6 IC7 IC16 IC17 IC21 IC41 = 74xx-us:74*139: Dual 2-line to 4-line DECODER/DEMULTIPLEXER
IC8 = linear:*555: TIMER
IC9-IC11 IC23 = 74xx-us:74*74: Dual D type positive edge triggered FLIP FLOP, preset and clear
IC12 IC18 = 74xx-eu:74*00: Quad 2-input NAND gate
IC13-IC15 = 74xx-us:74*180: 9-bit odd/even PARITY GENERATOR/CHECKER
IC19 IC22 = 74xx-us:74*07: Hex BUFFER, open collector high-voltage output
IC20 IC24 IC26 IC30 IC31 IC34 IC37 IC38 = 74xx-us:74*240: Octal BUFFER and LINE DRIVER, 3-state
IC25 IC29 IC32 IC36 = 74xx-us:74*138: 3-line to 8-line DECODER/DEMULTIPLEXER
IC27 = ic-package:DIL20: Dual In Line
IC28 IC35 = 74xx-us:74*244: Octal BUFFER and LINE DRIVER, 3-state
IC55 = 74xx-jameco:74*38: Quad 2-input NAND gate, open collector output
J2-J14 = jumper:J: Bridge
PAD1-PAD9 = wirepad:1,6/0,8: THROUGH-HOLE PAD
R1 R2 RA RB RL = rcl:R-US_: RESISTOR, American symbol
SV1 SV2 = con-lstb:MA13-2: PIN HEADER
SW1-SW4 = special:SW_DIP-8: DIP SWITCH

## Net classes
1 Power: width 0.508 mm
